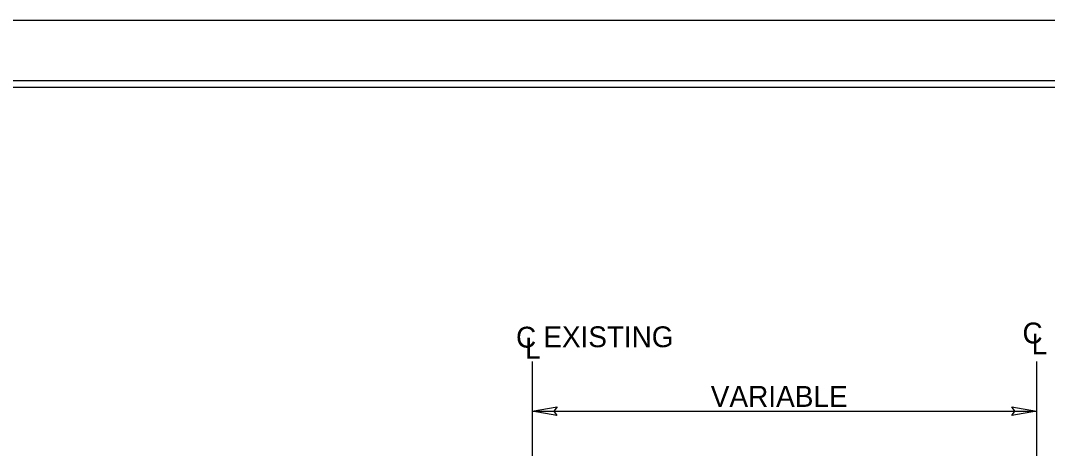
# Model space of a CAD drawing. Extents: x 957297 to 961629, y 830661 to 840840.
# Drawn here: x 959115.8 to 959498.6, y 836837.7 to 836997.1 of the extents above; entities that cross this region are included whole.
import ezdxf

# ---------------------------------------------------------------- set-up
doc = ezdxf.new("R2010")
doc.units = 0
for name, color, linetype in [('Default', 7, 'Continuous'), ('Old_Level_1', 7, 'Continuous'), ('Prop Dimension Text', 7, 'Continuous'), ('Sheet Plot Border Inside CELL', 7, 'Continuous'), ('Sheet Plot Border Outside CELL', 7, 'Continuous'), ('Sheet Typical CELL', 7, 'Continuous'), ('Typical Terminator CELL', 7, 'Continuous')]:
    doc.layers.add(name, color=color, linetype=linetype)

msp = doc.modelspace()

# ---------------------------------------------------------------- linework, layer by layer
at = {"layer": 'Default'}
for p, q in [((959306.49, 836870.09), (959306.49, 836825.83)), ((959494.54, 836870.09), (959494.54, 836821.89))]:
    msp.add_line(p, q, dxfattribs=at)
at = {"layer": 'Old_Level_1'}
msp.add_line((959306.49, 836851.64), (959494.54, 836851.64), dxfattribs=at)
at = {"layer": 'Sheet Plot Border Inside CELL'}
msp.add_lwpolyline([(960390.3, 836974.7), (958723.8, 836974.7), (958723.8, 835919.6), (960390.3, 835919.6)], close=True, dxfattribs=at)
at = {"layer": 'Sheet Plot Border Outside CELL'}
msp.add_lwpolyline([(960394.8, 836997.15), (958710.8, 836997.15), (958710.8, 835897.15), (960394.8, 835897.15)], close=True, dxfattribs=at)
at = {"layer": 'Sheet Typical CELL'}
msp.add_lwpolyline([(960377.8, 836972.15), (958877.8, 836972.15), (958877.8, 835922.15), (960377.8, 835922.15)], close=True, dxfattribs=at)
at = {"layer": 'Typical Terminator CELL'}
for points in [[(959315.71, 836850.06), (959306.49, 836851.64), (959315.76, 836853.28), (959314.58, 836851.64)], [(959485.32, 836853.23), (959494.54, 836851.64), (959485.27, 836850), (959486.44, 836851.64)]]:
    msp.add_lwpolyline(points, close=True, dxfattribs=at)

# ---------------------------------------------------------------- texts
at = {"layer": 'Prop Dimension Text'}
for s, height, p in [('C', 7.77, (959489.3, 836876.85)), ('C', 7.77, (959300.49, 836875.3)), ('EXISTING', 7.767, (959310.69, 836875.44)), ('L', 7.77, (959492.69, 836872.76)), ('L', 7.77, (959303.88, 836871.21)), ('VARIABLE', 7.801, (959373.08, 836853.21))]:
    msp.add_text(s, height=height, rotation=0, dxfattribs=at).set_placement(p)

doc.saveas('drawing.dxf')
